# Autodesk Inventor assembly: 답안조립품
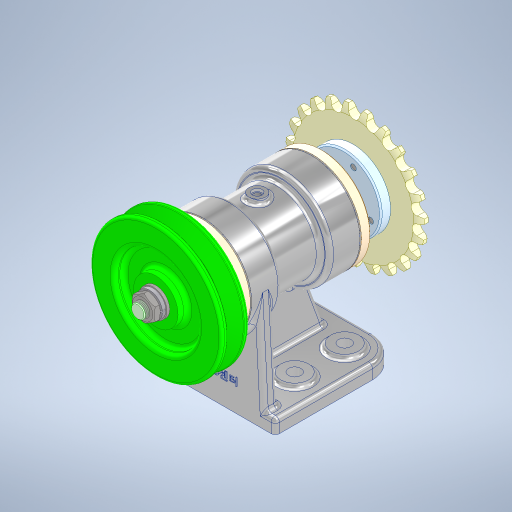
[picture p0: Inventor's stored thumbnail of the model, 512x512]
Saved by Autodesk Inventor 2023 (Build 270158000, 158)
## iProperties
Created: 2024-02
Part Number: 답안조립품
Document SubType Name: Assembly
Designer: home
Author: home
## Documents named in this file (18)
- C:\Users\home\Desktop\740204V1006\답안조립품.iam
- C:\Users\home\Desktop\740204V1006\본체.ipt
- C:\Users\home\Desktop\740204V1006\V-벨트풀리.ipt
- C:\Users\home\Desktop\740204V1006\가스켓.ipt
- C:\Users\home\Desktop\740204V1006\깊은 홈 볼 베어링 6204.ipt
- C:\Users\home\Desktop\740204V1006\스프로킷.ipt
- C:\Users\home\Desktop\740204V1006\스프링 와셔 M5.ipt
- C:\Users\home\Desktop\740204V1006\스프링 와셔 M10.ipt
- C:\Users\home\Desktop\740204V1006\앤드 캡.ipt
- C:\Users\home\Desktop\740204V1006\오일 실 20 32 5.ipt
- C:\Users\home\Desktop\740204V1006\육각 너트 M10x1.ipt
- C:\Users\home\Desktop\740204V1006\육각 소켓 머리 볼트 M4 x 10.ipt
- C:\Users\home\Desktop\740204V1006\육각 소켓 머리 볼트 M5 x 12.ipt
- C:\Users\home\Desktop\740204V1006\축.ipt
- C:\Users\home\Desktop\740204V1006\커버.ipt
- C:\Users\home\Desktop\740204V1006\평와셔 M10.ipt
- C:\Users\home\Desktop\740204V1006\평행 키 5x5x12.ipt
- C:\Users\home\Desktop\740204V1006\플랜지.ipt
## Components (4 placed, 3 different names)
1. V-벨트풀리:1 — 각도:3
2. 가스켓:1
3. 플랜지:1 — 각도:4
4. 가스켓:2
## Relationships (2: Angle 2)
- 각도:3 [Angle]: V-벨트풀리:1
- 각도:4 [Angle]: 플랜지:1
